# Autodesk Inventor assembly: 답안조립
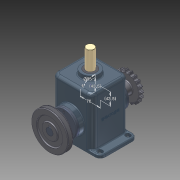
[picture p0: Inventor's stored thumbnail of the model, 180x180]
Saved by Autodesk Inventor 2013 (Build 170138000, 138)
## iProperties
Created: 2015-03
Part Number: 답안조립
Document SubType Name: Assembly
Designer: Administrator
Author: Administrator
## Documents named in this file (15)
- C:\Users\Administrator\Desktop\350306V1031\답안조립.iam
- C:\Users\Administrator\Desktop\350306V1031\본체.ipt
- C:\Users\Administrator\Desktop\350306V1031\M4x0.5.ipt
- C:\Users\Administrator\Desktop\350306V1031\V-벨트풀리.ipt
- C:\Users\Administrator\Desktop\350306V1031\멈춤링.ipt
- C:\Users\Administrator\Desktop\350306V1031\베어링 6205.ipt
- C:\Users\Administrator\Desktop\350306V1031\오일실.ipt
- C:\Users\Administrator\Desktop\350306V1031\커버.ipt
- C:\Users\Administrator\Desktop\350306V1031\키 8x8.ipt
- C:\Users\Administrator\Desktop\350306V1031\편심축.ipt
- C:\Users\Administrator\Desktop\350306V1031\가변스프링.ipt
- C:\Users\Administrator\Desktop\350306V1031\부시.ipt
- C:\Users\Administrator\Desktop\350306V1031\슬라이드.ipt
- C:\Users\Administrator\Desktop\350306V1031\체인 스프로킷.ipt
- C:\Users\Administrator\Desktop\350306V1031\멈춤나사 M5x0.5.ipt
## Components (9 placed, 4 different names)
1. V-벨트풀리:1 — 각도:4, 플러쉬:1
2. 가변스프링:1 — 각도:6
3. 5-체인 스프로킷:1 — 각도:7, 플러쉬:2
4. M4x0.5:1
5. M4x0.5:2
6. M4x0.5:3
7. M4x0.5:4
8. M4x0.5:5
9. M4x0.5:6
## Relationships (5: Angle 3, Flush 2)
- 각도:4 [Angle]: V-벨트풀리:1
- 플러쉬:1 [Flush]: V-벨트풀리:1
- 각도:6 [Angle]: 가변스프링:1
- 각도:7 [Angle]: 5-체인 스프로킷:1
- 플러쉬:2 [Flush]: 5-체인 스프로킷:1
